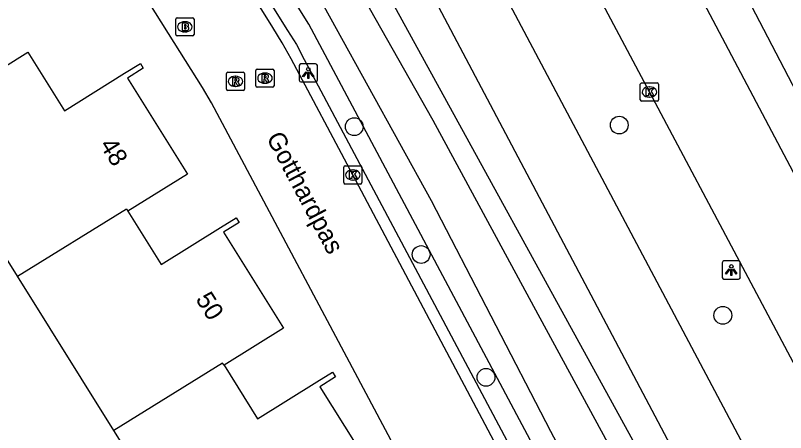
# Model space of a CAD drawing. Extents: x 158838 to 160074, y 386376 to 387776.
# Drawn here: x 159276.51 to 159318.88, y 386968.31 to 386991.27 of the extents above; entities that cross this region are included whole.
import ezdxf

# ---------------------------------------------------------------- set-up
doc = ezdxf.new("R2010")
doc.units = 0
for name, color, linetype in [('IMGEO_Berm_groen', 7, 'Continuous'), ('IMGEO_Boom', 7, 'Continuous'), ('IMGEO_Brandkraan', 7, 'Continuous'), ('IMGEO_Fietspad_gesloten', 7, 'Continuous'), ('IMGEO_Kolk', 7, 'Continuous'), ('IMGEO_Lichtpunt', 7, 'Continuous'), ('IMGEO_Openbare_ruimte_label', 7, 'Continuous'), ('IMGEO_Pand', 7, 'Continuous'), ('IMGEO_Pand_nummerreeks', 7, 'Continuous'), ('IMGEO_Rijbaan_lokaal_gesloten', 7, 'Continuous'), ('IMGEO_Rijbaan_lokaal_open', 7, 'Continuous'), ('IMGEO_Rioolput', 7, 'Continuous'), ('IMGEO_Verkeerseiland_open', 7, 'Continuous'), ('IMGEO_Waterloop', 7, 'Continuous')]:
    doc.layers.add(name, color=color, linetype=linetype)

msp = doc.modelspace()

# ---------------------------------------------------------------- linework, layer by layer
at = {"layer": 'IMGEO_Berm_groen'}
for points in [[(159285.483, 387013.434), (159292.854, 387000), (159314.774, 386960.051)], [(159322.893, 386933.968), (159292.65, 386990.788), (159286.899, 387000), (159280.408, 387010.398)]]:
    msp.add_lwpolyline(points, dxfattribs=at)
at = {"layer": 'IMGEO_Boom'}
for centre in [(159309.731, 386985.236), (159295.155, 386985.147), (159298.833, 386978.111), (159315.43, 386974.762), (159302.403, 386971.352)]:
    msp.add_circle(centre, 0.489, dxfattribs=at)
at = {"layer": 'IMGEO_Brandkraan'}
for p, q in [((159285.339, 386990.214), (159285.339, 386991.066)), ((159285.414, 386991.14), (159286.266, 386991.14)), ((159285.827, 386990.92), (159285.852, 386990.92)), ((159286.34, 386991.066), (159286.34, 386990.214)), ((159285.85, 386990.36), (159285.825, 386990.36)), ((159286.266, 386990.14), (159285.414, 386990.14))]:
    msp.add_line(p, q, dxfattribs=at)
for points in [[(159285.339, 386990.214), (159285.339, 386991.066)], [(159285.414, 386991.14), (159286.266, 386991.14)], [(159285.687, 386990.84), (159285.687, 386990.44), (159285.9, 386990.44)], [(159285.918, 386990.84), (159285.687, 386990.84)], [(159285.866, 386990.759), (159285.812, 386990.759), (159285.812, 386990.683)], [(159286.34, 386991.066), (159286.34, 386990.214)], [(159285.812, 386990.683), (159285.865, 386990.683)], [(159285.874, 386990.607), (159285.812, 386990.607), (159285.812, 386990.526)], [(159285.812, 386990.526), (159285.874, 386990.526)], [(159286.266, 386990.14), (159285.414, 386990.14)]]:
    msp.add_lwpolyline(points, dxfattribs=at)
for centre, radius, start, end in [((159285.416, 386991.064), 0.0765, 91.552, 178.448), ((159285.416, 386991.064), 0.0765, 91.552, 178.448), ((159285.867, 386990.721), 0.0379, 267.8285, 90.9355), ((159285.922, 386990.695), 0.145, 59.4692, 91.5367), ((159285.947, 386990.742), 0.0922, 285.5137, 58.1501), ((159286.264, 386991.064), 0.0765, 1.552, 88.448), ((159286.264, 386991.064), 0.0765, 1.552, 88.448), ((159285.875, 386990.566), 0.0404, 269.8759, 90.5077), ((159285.906, 386990.691), 0.251, 268.6676, 293.5347), ((159285.952, 386990.55), 0.105, 301.3115, 78.989), ((159285.416, 386990.216), 0.0765, 181.552, 268.448), ((159285.416, 386990.216), 0.0765, 181.552, 268.448), ((159286.264, 386990.216), 0.0765, 271.552, 358.448), ((159286.264, 386990.216), 0.0765, 271.552, 358.448)]:
    msp.add_arc(centre, radius, start, end, dxfattribs=at)
for centre, major_axis, ratio, start_param, end_param in [((159285.826, 386990.64), (-0.387, 0.002), 0.722429, 4.712389, 7.853982), ((159285.851, 386990.64), (-0.39, 0.002), 0.717154, 1.570796, 4.712389)]:
    msp.add_ellipse(centre, major_axis=major_axis, ratio=ratio, start_param=start_param, end_param=end_param, dxfattribs=at)
at = {"layer": 'IMGEO_Fietspad_gesloten'}
for points in [[(159292.669, 387012.696), (159299.401, 387000), (159318.953, 386963.127)], [(159315.911, 386961.271), (159295.447, 387000), (159289.601, 387011.063)]]:
    msp.add_lwpolyline(points, dxfattribs=at)
at = {"layer": 'IMGEO_Kolk'}
for p, q in [((159310.889, 386986.628), (159310.889, 386987.48)), ((159310.964, 386987.554), (159311.816, 386987.554)), ((159311.89, 386987.48), (159311.89, 386986.628)), ((159311.377, 386987.334), (159311.402, 386987.334)), ((159311.816, 386986.554), (159310.964, 386986.554)), ((159311.4, 386986.774), (159311.375, 386986.774)), ((159294.577, 386982.066), (159294.577, 386982.918)), ((159294.652, 386982.992), (159295.504, 386982.992)), ((159295.065, 386982.772), (159295.09, 386982.772)), ((159295.578, 386982.918), (159295.578, 386982.066)), ((159295.504, 386981.992), (159294.652, 386981.992)), ((159295.088, 386982.212), (159295.063, 386982.212))]:
    msp.add_line(p, q, dxfattribs=at)
for points in [[(159310.889, 386986.628), (159310.889, 386987.48)], [(159310.964, 386987.554), (159311.816, 386987.554)], [(159311.89, 386987.48), (159311.89, 386986.628)], [(159311.21, 386987.254), (159311.333, 386987.254), (159311.333, 386987.103), (159311.463, 386987.254), (159311.627, 386987.254), (159311.481, 386987.103), (159311.634, 386986.854), (159311.482, 386986.854), (159311.397, 386987.018), (159311.333, 386986.951), (159311.333, 386986.854), (159311.21, 386986.854), (159311.21, 386987.254)], [(159311.816, 386986.554), (159310.964, 386986.554)], [(159294.577, 386982.066), (159294.577, 386982.918)], [(159294.652, 386982.992), (159295.504, 386982.992)], [(159294.898, 386982.692), (159295.021, 386982.692), (159295.021, 386982.541), (159295.151, 386982.692), (159295.315, 386982.692), (159295.169, 386982.541), (159295.322, 386982.292), (159295.17, 386982.292), (159295.085, 386982.456), (159295.021, 386982.389), (159295.021, 386982.292), (159294.898, 386982.292), (159294.898, 386982.692)], [(159295.578, 386982.918), (159295.578, 386982.066)], [(159295.504, 386981.992), (159294.652, 386981.992)]]:
    msp.add_lwpolyline(points, dxfattribs=at)
for centre, start, end in [((159310.966, 386987.478), 91.552, 178.448), ((159310.966, 386987.478), 91.552, 178.448), ((159311.814, 386987.478), 1.552, 88.448), ((159311.814, 386987.478), 1.552, 88.448), ((159310.966, 386986.63), 181.552, 268.448), ((159310.966, 386986.63), 181.552, 268.448), ((159311.814, 386986.63), 271.552, 358.448), ((159311.814, 386986.63), 271.552, 358.448), ((159294.654, 386982.916), 91.552, 178.448), ((159294.654, 386982.916), 91.552, 178.448), ((159295.502, 386982.916), 1.552, 88.448), ((159295.502, 386982.916), 1.552, 88.448), ((159294.654, 386982.068), 181.552, 268.448), ((159294.654, 386982.068), 181.552, 268.448), ((159295.502, 386982.068), 271.552, 358.448), ((159295.502, 386982.068), 271.552, 358.448)]:
    msp.add_arc(centre, 0.0765, start, end, dxfattribs=at)
for centre, major_axis, ratio, start_param, end_param in [((159311.376, 386987.054), (-0.387, 0.002), 0.722429, 4.712389, 7.853982), ((159311.401, 386987.054), (-0.39, 0.002), 0.717154, 1.570796, 4.712389), ((159295.064, 386982.492), (-0.387, 0.002), 0.722429, 4.712389, 7.853982), ((159295.089, 386982.492), (-0.39, 0.002), 0.717154, 1.570796, 4.712389)]:
    msp.add_ellipse(centre, major_axis=major_axis, ratio=ratio, start_param=start_param, end_param=end_param, dxfattribs=at)
at = {"layer": 'IMGEO_Lichtpunt'}
for p, q in [((159292.128, 386988.511), (159292.128, 386987.704)), ((159292.128, 386988.511), (159292.128, 386987.704)), ((159293.03, 386988.606), (159292.222, 386988.606)), ((159293.03, 386988.606), (159292.222, 386988.606)), ((159293.124, 386987.704), (159293.124, 386988.511)), ((159293.124, 386987.704), (159293.124, 386988.511)), ((159292.222, 386987.61), (159293.03, 386987.61)), ((159292.222, 386987.61), (159293.03, 386987.61)), ((159315.397, 386977.662), (159315.397, 386976.855)), ((159315.397, 386977.662), (159315.397, 386976.855)), ((159316.299, 386977.757), (159315.491, 386977.757)), ((159316.299, 386977.757), (159315.491, 386977.757)), ((159316.393, 386976.855), (159316.393, 386977.662)), ((159316.393, 386976.855), (159316.393, 386977.662)), ((159315.491, 386976.761), (159316.299, 386976.761)), ((159315.491, 386976.761), (159316.299, 386976.761))]:
    msp.add_line(p, q, dxfattribs=at)
for points in [[(159292.502, 386988.175), (159292.541, 386988.147), (159292.353, 386987.885), (159292.315, 386987.912), (159292.502, 386988.175)], [(159292.604, 386988.127), (159292.651, 386988.127), (159292.651, 386987.805), (159292.604, 386987.805), (159292.604, 386988.127)], [(159292.714, 386988.147), (159292.752, 386988.174), (159292.939, 386987.912), (159292.9, 386987.884), (159292.714, 386988.147)], [(159315.771, 386977.326), (159315.81, 386977.298), (159315.622, 386977.036), (159315.584, 386977.063), (159315.771, 386977.326)], [(159315.873, 386977.278), (159315.92, 386977.278), (159315.92, 386976.956), (159315.873, 386976.956), (159315.873, 386977.278)], [(159315.983, 386977.298), (159316.021, 386977.325), (159316.208, 386977.063), (159316.169, 386977.035), (159315.983, 386977.298)]]:
    msp.add_lwpolyline(points, dxfattribs=at)
for centre in [(159292.627, 386988.309), (159315.896, 386977.46)]:
    msp.add_circle(centre, 0.0994, dxfattribs=at)
for centre, start, end in [((159292.222, 386988.511), 90, 180), ((159292.222, 386988.511), 90, 180), ((159293.03, 386988.511), 0, 90), ((159293.03, 386988.511), 0, 90), ((159292.222, 386987.704), 180, 270), ((159292.222, 386987.704), 180, 270), ((159293.03, 386987.704), 270, 0), ((159293.03, 386987.704), 270, 360), ((159315.491, 386977.662), 90, 180), ((159315.491, 386977.662), 90, 180), ((159316.299, 386977.662), 0, 90), ((159316.299, 386977.662), 0, 90), ((159315.491, 386976.855), 180, 270), ((159315.491, 386976.855), 180, 270), ((159316.299, 386976.855), 270, 0), ((159316.299, 386976.855), 270, 360)]:
    msp.add_arc(centre, 0.0946, start, end, dxfattribs=at)
at = {"layer": 'IMGEO_Pand'}
for points in [[(159276.622, 386976.926), (159271.244, 386985.523), (159277.196, 386989.247), (159279.211, 386986.025), (159282.518, 386988.093), (159283.396, 386988.625), (159283.551, 386988.359), (159282.688, 386987.82), (159285.986, 386982.542), (159282.707, 386980.493)], [(159276.622, 386976.926), (159282.622, 386980.629), (159282.707, 386980.493)], [(159282.707, 386980.493), (159284.533, 386977.569), (159287.796, 386979.607), (159288.657, 386980.13), (159288.818, 386979.865), (159287.967, 386979.333), (159291.265, 386974.056), (159287.993, 386972.012)], [(159281.936, 386968.43), (159276.622, 386976.926)], [(159287.993, 386972.012), (159287.914, 386972.139), (159281.936, 386968.43)], [(159287.993, 386972.012), (159289.831, 386969.071), (159293.094, 386971.11), (159293.965, 386971.641), (159294.125, 386971.373), (159293.265, 386970.836), (159296.557, 386965.567), (159292.726, 386963.174)], [(159287.243, 386959.946), (159281.936, 386968.43)]]:
    msp.add_lwpolyline(points, dxfattribs=at)
at = {"layer": 'IMGEO_Rijbaan_lokaal_gesloten'}
for points in [[(159303.204, 387018.31), (159312.737, 387000), (159328.89, 386968.974)], [(159329.667, 386963.05), (159310.146, 387000), (159301.083, 387017.155)], [(159296.643, 387014.832), (159301.816, 387005.114), (159304.527, 387000), (159311.391, 386987.054), (159321.919, 386967.225), (159327.625, 386956.214)]]:
    msp.add_lwpolyline(points, dxfattribs=at)
at = {"layer": 'IMGEO_Rijbaan_lokaal_open'}
for points in [[(159322.715, 386930.535), (159321.43, 386932.941), (159304.466, 386964.768), (159295.073, 386982.492), (159291.692, 386988.882), (159291.192, 386989.757), (159290.67, 386990.608), (159286.562, 386997.204), (159284.795, 387000), (159275.864, 387014.134), (159275.266, 387015.086)], [(159317.722, 386929.245), (159312.67, 386938.746), (159307.356, 386948.741), (159287.3, 386986.46), (159286.81, 386987.307), (159278.827, 387000), (159271.75, 387011.252)]]:
    msp.add_lwpolyline(points, dxfattribs=at)
at = {"layer": 'IMGEO_Rioolput'}
for p, q in [((159289.741, 386987.392), (159289.741, 386988.244)), ((159289.816, 386988.318), (159290.668, 386988.318)), ((159290.742, 386988.244), (159290.742, 386987.392)), ((159288.123, 386987.214), (159288.123, 386988.066)), ((159288.198, 386988.14), (159289.05, 386988.14)), ((159288.611, 386987.92), (159288.636, 386987.92)), ((159289.124, 386988.066), (159289.124, 386987.214)), ((159290.229, 386988.098), (159290.254, 386988.098)), ((159288.634, 386987.36), (159288.609, 386987.36)), ((159290.252, 386987.538), (159290.227, 386987.538)), ((159289.05, 386987.14), (159288.198, 386987.14)), ((159290.668, 386987.318), (159289.816, 386987.318))]:
    msp.add_line(p, q, dxfattribs=at)
for points in [[(159289.741, 386987.392), (159289.741, 386988.244)], [(159289.816, 386988.318), (159290.668, 386988.318)], [(159290.742, 386988.244), (159290.742, 386987.392)], [(159288.123, 386987.214), (159288.123, 386988.066)], [(159288.198, 386988.14), (159289.05, 386988.14)], [(159288.712, 386987.838), (159288.46, 386987.84), (159288.46, 386987.44)], [(159289.124, 386988.066), (159289.124, 386987.214)], [(159290.33, 386988.016), (159290.078, 386988.018), (159290.078, 386987.618)], [(159290.078, 386987.618), (159290.202, 386987.618), (159290.202, 386987.78), (159290.213, 386987.78)], [(159290.256, 386987.937), (159290.202, 386987.937), (159290.202, 386987.856)], [(159290.202, 386987.856), (159290.254, 386987.856)], [(159288.46, 386987.44), (159288.584, 386987.44), (159288.584, 386987.602), (159288.595, 386987.602)], [(159288.638, 386987.759), (159288.584, 386987.759), (159288.584, 386987.678)], [(159288.584, 386987.678), (159288.636, 386987.678)], [(159288.642, 386987.573), (159288.713, 386987.44), (159288.853, 386987.44), (159288.788, 386987.566)], [(159290.26, 386987.751), (159290.331, 386987.618), (159290.471, 386987.618), (159290.406, 386987.744)], [(159289.05, 386987.14), (159288.198, 386987.14)], [(159290.668, 386987.318), (159289.816, 386987.318)]]:
    msp.add_lwpolyline(points, dxfattribs=at)
for centre, radius, start, end in [((159289.818, 386988.242), 0.0765, 91.552, 178.448), ((159289.818, 386988.242), 0.0765, 91.552, 178.448), ((159290.666, 386988.242), 0.0765, 1.552, 88.448), ((159290.666, 386988.242), 0.0765, 1.552, 88.448), ((159288.2, 386988.064), 0.0765, 91.552, 178.448), ((159288.2, 386988.064), 0.0765, 91.552, 178.448), ((159288.711, 386987.728), 0.109, 350.3612, 89.416), ((159289.048, 386988.064), 0.0765, 1.552, 88.448), ((159289.048, 386988.064), 0.0765, 1.552, 88.448), ((159290.212, 386987.727), 0.0533, 26.0293, 88.6989), ((159290.238, 386988.045), 0.19, 274.7715, 282.9687), ((159290.262, 386987.841), 0.0964, 77.0061, 93.1865), ((159290.276, 386987.898), 0.0378, 276.6634, 79.6772), ((159290.329, 386987.906), 0.109, 350.3612, 89.416), ((159290.327, 386987.906), 0.112, 277.5842, 350.9817), ((159290.311, 386987.691), 0.108, 29.5134, 73.7905), ((159288.594, 386987.549), 0.0533, 26.0293, 88.6989), ((159288.62, 386987.867), 0.19, 274.7715, 282.9687), ((159288.644, 386987.663), 0.0964, 77.0061, 93.1865), ((159288.658, 386987.72), 0.0378, 276.6634, 79.6772), ((159288.709, 386987.728), 0.112, 277.5842, 350.9817), ((159288.693, 386987.513), 0.108, 29.5134, 73.7905), ((159289.818, 386987.394), 0.0765, 181.552, 268.448), ((159289.818, 386987.394), 0.0765, 181.552, 268.448), ((159290.666, 386987.394), 0.0765, 271.552, 358.448), ((159290.666, 386987.394), 0.0765, 271.552, 358.448), ((159288.2, 386987.216), 0.0765, 181.552, 268.448), ((159288.2, 386987.216), 0.0765, 181.552, 268.448), ((159289.048, 386987.216), 0.0765, 271.552, 358.448), ((159289.048, 386987.216), 0.0765, 271.552, 358.448)]:
    msp.add_arc(centre, radius, start, end, dxfattribs=at)
for centre, major_axis, ratio, start_param, end_param in [((159288.61, 386987.64), (-0.387, 0.002), 0.722429, 4.712389, 7.853982), ((159288.635, 386987.64), (-0.39, 0.002), 0.717154, 1.570796, 4.712389), ((159290.228, 386987.818), (-0.387, 0.002), 0.722429, 4.712389, 7.853982), ((159290.253, 386987.818), (-0.39, 0.002), 0.717154, 1.570796, 4.712389)]:
    msp.add_ellipse(centre, major_axis=major_axis, ratio=ratio, start_param=start_param, end_param=end_param, dxfattribs=at)
at = {"layer": 'IMGEO_Verkeerseiland_open'}
msp.add_lwpolyline([(159275.437, 387015.961), (159285.506, 387000), (159287.099, 386997.475), (159291.489, 386990.45), (159291.972, 386989.668), (159292.393, 386988.851), (159323.247, 386930.836), (159322.715, 386930.535)], dxfattribs=at)
at = {"layer": 'IMGEO_Waterloop'}
for points in [[(159281.734, 387011.301), (159283.78, 387012.499), (159284.642, 387011.966), (159292.24, 386998.311), (159299.468, 386985.497), (159305.012, 386975.271), (159315.73, 386955.518)], [(159323.133, 386935.169), (159318.205, 386944.963), (159313.318, 386954.471), (159305.967, 386968.372), (159299.396, 386981.062), (159292.435, 386993.711), (159284.776, 387005.867), (159281.675, 387011.026)]]:
    msp.add_lwpolyline(points, dxfattribs=at)

# ---------------------------------------------------------------- texts
at = {"layer": 'IMGEO_Openbare_ruimte_label'}
msp.add_text('Gotthardpas', height=1, rotation=297.9747, dxfattribs=at).set_placement((159290.293, 386984.541))
at = {"layer": 'IMGEO_Pand_nummerreeks'}
for s, rotation, p in [('48', 301.9995, (159281.12, 386984.141)), ('50', 302.0044, (159286.399, 386975.654))]:
    msp.add_text(s, height=1, rotation=rotation, dxfattribs=at).set_placement(p)

doc.saveas('drawing.dxf')
